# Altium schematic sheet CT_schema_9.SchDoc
size 274 x 160 mm
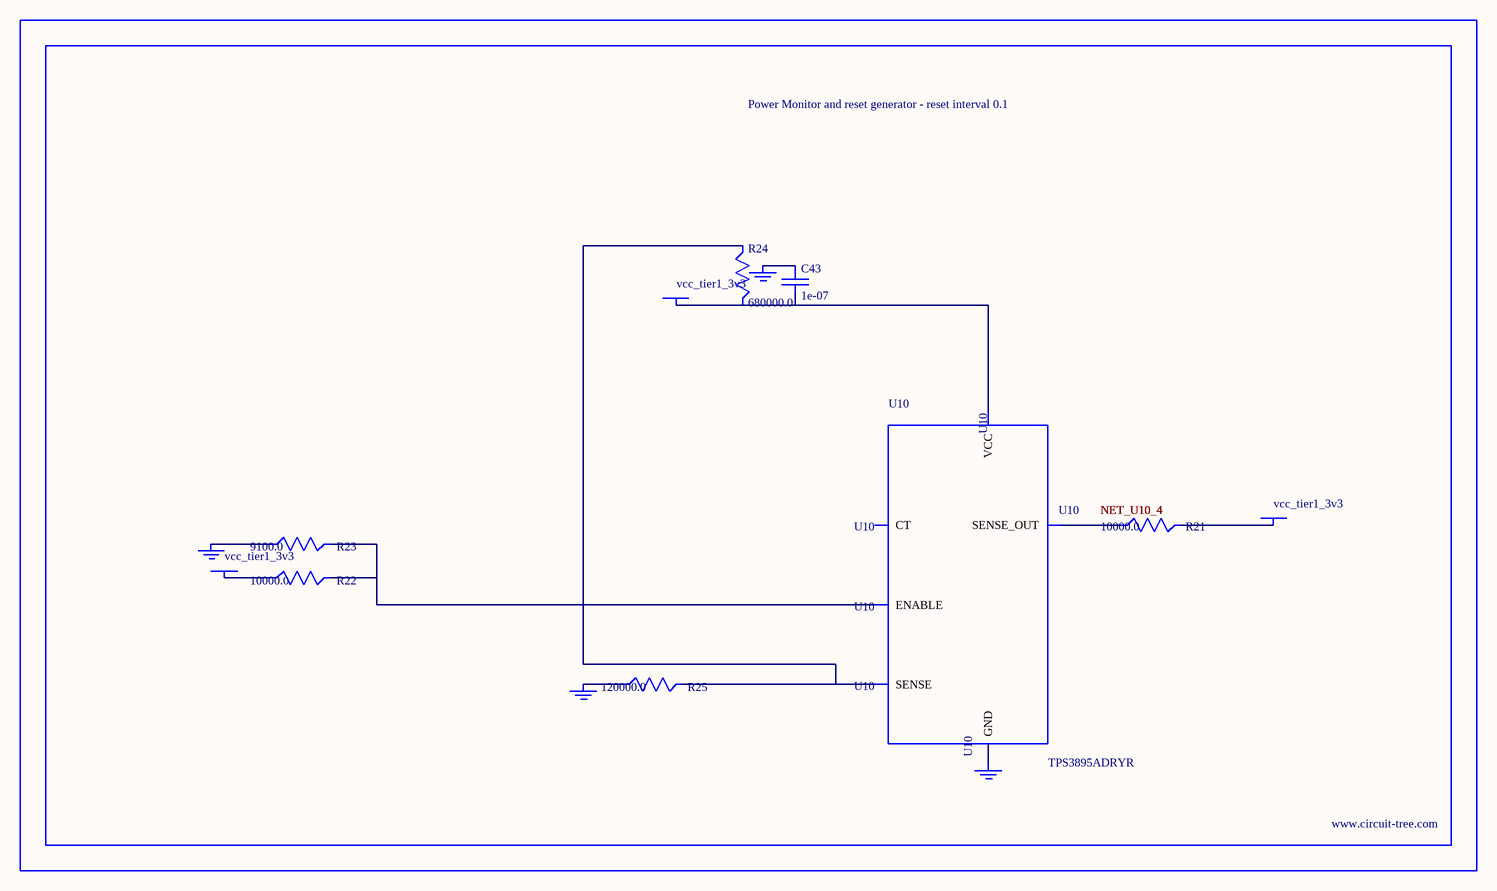
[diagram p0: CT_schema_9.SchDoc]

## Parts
BORDER8  (no value)
C43  1e-07  [C0402]
GND_INSTANCE_8_0  (no value)
GND_INSTANCE_8_1  (no value)
GND_INSTANCE_8_2  (no value)
GND_INSTANCE_8_3  (no value)
POWER_INSTANCE_8_0  vcc_tier1_3v3
POWER_INSTANCE_8_1  vcc_tier1_3v3
POWER_INSTANCE_8_2  vcc_tier1_3v3
R21  10000.0  [R0603]
R22  10000.0  [R0603]
R23  9100.0  [R0603]
R24  680000.0  [R0603]
R25  120000.0  [R0603]
U10  TPS3895ADRYR  [SON-6]

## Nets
NetC43_1: C43.1 GND_INSTANCE_8_2.0(GND)
NetC43_2: C43.2 POWER_INSTANCE_8_2.0(PWR) R24.2 U10.6(VCC)
NetGND_INSTANCE_8_0_0: GND_INSTANCE_8_0.0(GND) R23.1
NetGND_INSTANCE_8_1_0: GND_INSTANCE_8_1.0(GND) R25.1
NetGND_INSTANCE_8_3_0: GND_INSTANCE_8_3.0(GND) U10.2(GND)
NetPOWER_INSTANCE_8_0_0: POWER_INSTANCE_8_0.0(PWR) R22.1
NetPOWER_INSTANCE_8_1_0: POWER_INSTANCE_8_1.0(PWR) R21.2
NetR21_1: R21.1 U10.4(SENSE_OUT)
NetR22_2: R22.2 R23.2 U10.1(ENABLE)
NetR24_1: R24.1 R25.2 U10.3(SENSE)

Not connected (* = marked no-connect by the designer): U10 5(CT)

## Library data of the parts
BORDER8 = BORDER_PAGE8
C43 = C0402C104K3RACTU
GND_INSTANCE_8_0-GND_INSTANCE_8_3 = GND
POWER_INSTANCE_8_0-POWER_INSTANCE_8_2 = PWR
R21 R22 = RC0603JR-0710KL
R23 = RC0603JR-079K1L
R24 = RC0603JR-07680KL
R25 = RC0603JR-07120KL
